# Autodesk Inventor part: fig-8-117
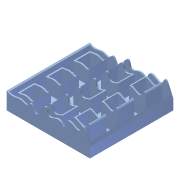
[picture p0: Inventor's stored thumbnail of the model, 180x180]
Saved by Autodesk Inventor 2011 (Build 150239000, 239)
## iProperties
Shininess: 64.0
Length Units: 11269
Angle Units: 11279
Time Units: 11290
Mass Units: 11283
Length Display Precision: 3
Angle Display Precision: 2
Compacted: True
Part Number: fig-8-117
Document SubType Name: Modeling
Created: 2002-12
Designer: deepak
Density: 1 g/cm^3
Density: 0.0
Volumn: 0.0
Area: 0.0
PropertySet Name: Model Information
Control State: 0
Master: False
Checked Out: False
Author: deepak
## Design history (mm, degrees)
sketch "Sketch1"
  geometry: L1 (-32.188, 30.089)-(27.812, 30.089); L2 (27.812, 30.089)-(27.812, -29.911); L3 (27.812, -29.911)-(-32.188, -29.911); L4 (-32.188, -29.911)-(-32.188, 30.089)
  constraints: 8 end point, 2 parallel, 1 horizontal, 1 perpendicular
  dimensions: "d0" = 60 distance of L1.start L1.end; "d1" = 60 distance of L3.end L1.start
extrude "Extrusion1" new body sketch "Sketch1" stored distance "d2" = 20; taper "d3" = 0 deg
sketch "Sketch5"
  geometry: L1 (-27.812, 30.089)-(32.188, 30.089) reference; L2 (-27.812, -29.911)-(-27.812, 30.089) reference; L3 (-22.812, 25.089)-(-12.812, 25.089); L4 (-12.812, 25.089)-(-12.812, 15.089); L5 (-12.812, 15.089)-(-22.812, 15.089); L6 (-22.812, 15.089)-(-22.812, 25.089)
  constraints: 8 end point, 2 parallel, 1 horizontal, 1 perpendicular
  dimensions: "d8" = 10 distance of L3.start L3.end; "d9" = 10 distance of L5.end L3.start; "d10" = 5 distance between parallel lines of L2 L6; "d11" = 5 distance between parallel lines of L1 L3
extrude "Extrusion2" cut sketch "Sketch5" distance "d12" = 50; taper "d13" = 0 deg
pattern_linear "Rectangular Pattern1" dims "d16" = 20
shell "Shell2" dims "d21" = 1
sketch "Sketch2"
  geometry: 17 further points
  constraints: 17 other
extrude_surface "ExtrusionSrf1" sketch "Sketch2" dims "d4" = 70, "d5" = 0
split "Split2"
body "Solid1"
body "Srf1"
